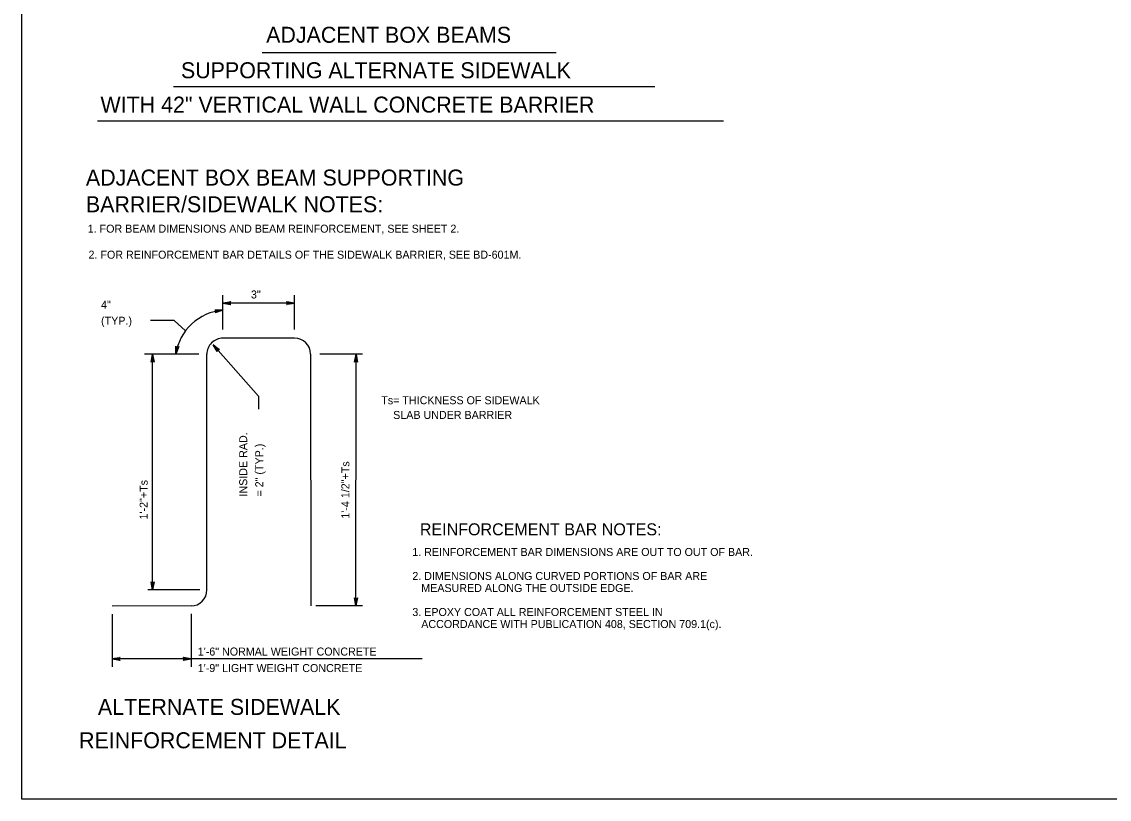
# Model space of a CAD drawing. Extents: x 639331 to 643089, y 299088 to 300975.
# Drawn here: x 641433.1 to 641840.8, y 299696.7 to 299988 of the extents above; entities that cross this region are included whole.
import ezdxf

# ---------------------------------------------------------------- set-up
doc = ezdxf.new("R2010")
doc.units = 0
doc.layers.add('1', color=7, linetype='Continuous')

msp = doc.modelspace()

# ---------------------------------------------------------------- linework, layer by layer
at = {"layer": '1'}
for p, q in [((641433.06, 299696.66), (641433.06, 300260.66)), ((641523.14, 299976.53), (641633.39, 299976.53)), ((641490, 299963.78), (641670.45, 299963.78)), ((641461.51, 299950.91), (641696.11, 299950.91)), ((641508.48, 299872.7), (641508.48, 299885.56)), ((641535.36, 299882.56), (641508.48, 299882.56)), ((641535.36, 299872.7), (641535.36, 299885.56)), ((641490.17, 299876.05), (641481.35, 299876.05)), ((641494.49, 299872.21), (641490.17, 299876.05)), ((641521.83, 299847.64), (641504.83, 299866.99)), ((641535.36, 299869.43), (641508.47, 299869.43)), ((641499.47, 299863.42), (641479.1, 299863.42)), ((641482.1, 299775.08), (641482.1, 299863.42)), ((641502.5, 299775.08), (641502.47, 299863.42)), ((641541.36, 299863.43), (641541.39, 299769.1)), ((641560.86, 299863.42), (641544.85, 299863.42)), ((641558.37, 299769.1), (641558.38, 299863.42)), ((641521.83, 299847.64), (641521.83, 299842.81)), ((641499.79, 299775.08), (641480.28, 299775.08)), ((641496.52, 299769.08), (641467, 299768.99)), ((641560.86, 299769.1), (641543.32, 299769.1)), ((641467, 299765.99), (641467, 299746.23)), ((641496.52, 299766.1), (641496.52, 299746.23)), ((641583.13, 299749.23), (641467, 299749.23)), ((642219.06, 299696.66), (641433.06, 299696.66))]:
    msp.add_line(p, q, dxfattribs=at)
for points in [[(641508.48, 299882.56), (641511.46, 299883.12), (641511.34, 299883.04), (641511.23, 299882.96), (641511.17, 299882.86), (641511.11, 299882.76), (641511.09, 299882.66), (641511.08, 299882.56), (641511.09, 299882.46), (641511.11, 299882.36), (641511.17, 299882.26), (641511.23, 299882.16), (641511.34, 299882.08), (641511.46, 299882), (641508.48, 299882.56), (641511.34, 299882.08), (641511.23, 299882.16), (641508.48, 299882.56), (641511.17, 299882.26), (641511.11, 299882.36), (641508.48, 299882.56), (641511.09, 299882.46), (641511.08, 299882.56), (641508.48, 299882.56), (641511.09, 299882.66), (641511.11, 299882.76), (641508.48, 299882.56), (641511.17, 299882.86), (641511.23, 299882.96), (641508.48, 299882.56), (641511.34, 299883.04)], [(641535.36, 299882.56), (641532.38, 299882), (641532.5, 299882.08), (641532.61, 299882.16), (641532.67, 299882.26), (641532.73, 299882.36), (641532.75, 299882.46), (641532.76, 299882.56), (641532.75, 299882.66), (641532.73, 299882.76), (641532.67, 299882.86), (641532.61, 299882.96), (641532.5, 299883.04), (641532.38, 299883.12), (641535.36, 299882.56), (641532.5, 299883.04), (641532.61, 299882.96), (641535.36, 299882.56), (641532.67, 299882.86), (641532.73, 299882.76), (641535.36, 299882.56), (641532.75, 299882.66), (641532.76, 299882.56), (641535.36, 299882.56), (641532.75, 299882.46), (641532.73, 299882.36), (641535.36, 299882.56), (641532.67, 299882.26), (641532.61, 299882.16), (641535.36, 299882.56), (641532.5, 299882.08)], [(641508.48, 299879.89), (641505.6, 299878.93), (641505.7, 299879.03), (641505.8, 299879.12), (641505.85, 299879.23), (641505.89, 299879.33), (641505.9, 299879.44), (641505.9, 299879.54), (641505.87, 299879.63), (641505.84, 299879.73), (641505.77, 299879.82), (641505.69, 299879.91), (641505.57, 299879.98), (641505.44, 299880.04), (641508.48, 299879.89), (641505.57, 299879.98), (641505.69, 299879.91), (641508.48, 299879.89), (641505.77, 299879.82), (641505.84, 299879.73), (641508.48, 299879.89), (641505.87, 299879.63), (641505.9, 299879.54), (641508.48, 299879.89), (641505.9, 299879.44), (641505.89, 299879.33), (641508.48, 299879.89), (641505.85, 299879.23), (641505.8, 299879.12), (641508.48, 299879.89), (641505.7, 299879.03)], [(641490.8, 299863.42), (641490.8, 299866.46), (641490.86, 299866.33), (641490.92, 299866.2), (641491.01, 299866.12), (641491.09, 299866.05), (641491.19, 299866.01), (641491.28, 299865.98), (641491.38, 299865.97), (641491.49, 299865.97), (641491.59, 299866.01), (641491.7, 299866.05), (641491.8, 299866.15), (641491.9, 299866.25), (641490.8, 299863.42), (641491.8, 299866.15), (641491.7, 299866.05), (641490.8, 299863.42), (641491.59, 299866.01), (641491.49, 299865.97), (641490.8, 299863.42), (641491.38, 299865.97), (641491.28, 299865.98), (641490.8, 299863.42), (641491.19, 299866.01), (641491.09, 299866.05), (641490.8, 299863.42), (641491.01, 299866.12), (641490.92, 299866.2), (641490.8, 299863.42), (641490.86, 299866.33)], [(641504.83, 299866.99), (641507.22, 299865.12), (641507.08, 299865.15), (641506.95, 299865.19), (641506.83, 299865.16), (641506.72, 299865.14), (641506.63, 299865.09), (641506.55, 299865.04), (641506.48, 299864.96), (641506.42, 299864.88), (641506.38, 299864.77), (641506.35, 299864.66), (641506.36, 299864.52), (641506.38, 299864.38), (641504.83, 299866.99), (641506.36, 299864.52), (641506.35, 299864.66), (641504.83, 299866.99), (641506.38, 299864.77), (641506.42, 299864.88), (641504.83, 299866.99), (641506.48, 299864.96), (641506.55, 299865.04), (641504.83, 299866.99), (641506.63, 299865.09), (641506.72, 299865.14), (641504.83, 299866.99), (641506.83, 299865.16), (641506.95, 299865.19), (641504.83, 299866.99), (641507.08, 299865.15)], [(641482.1, 299863.42), (641482.66, 299860.44), (641482.58, 299860.55), (641482.5, 299860.67), (641482.4, 299860.73), (641482.3, 299860.79), (641482.2, 299860.8), (641482.1, 299860.82), (641482, 299860.8), (641481.9, 299860.79), (641481.8, 299860.73), (641481.7, 299860.67), (641481.62, 299860.55), (641481.54, 299860.44), (641482.1, 299863.42), (641481.62, 299860.55), (641481.7, 299860.67), (641482.1, 299863.42), (641481.8, 299860.73), (641481.9, 299860.79), (641482.1, 299863.42), (641482, 299860.8), (641482.1, 299860.82), (641482.1, 299863.42), (641482.2, 299860.8), (641482.3, 299860.79), (641482.1, 299863.42), (641482.4, 299860.73), (641482.5, 299860.67), (641482.1, 299863.42), (641482.58, 299860.55)], [(641558.38, 299863.42), (641558.94, 299860.44), (641558.86, 299860.55), (641558.78, 299860.67), (641558.68, 299860.73), (641558.58, 299860.79), (641558.48, 299860.8), (641558.38, 299860.82), (641558.28, 299860.8), (641558.18, 299860.79), (641558.08, 299860.73), (641557.98, 299860.67), (641557.9, 299860.55), (641557.82, 299860.44), (641558.38, 299863.42), (641557.9, 299860.55), (641557.98, 299860.67), (641558.38, 299863.42), (641558.08, 299860.73), (641558.18, 299860.79), (641558.38, 299863.42), (641558.28, 299860.8), (641558.38, 299860.82), (641558.38, 299863.42), (641558.48, 299860.8), (641558.58, 299860.79), (641558.38, 299863.42), (641558.68, 299860.73), (641558.78, 299860.67), (641558.38, 299863.42), (641558.86, 299860.55)], [(641482.1, 299775.08), (641481.54, 299778.07), (641481.62, 299777.95), (641481.7, 299777.84), (641481.8, 299777.78), (641481.9, 299777.72), (641482, 299777.7), (641482.1, 299777.68), (641482.2, 299777.7), (641482.3, 299777.72), (641482.4, 299777.78), (641482.5, 299777.84), (641482.58, 299777.95), (641482.66, 299778.07), (641482.1, 299775.08), (641482.58, 299777.95), (641482.5, 299777.84), (641482.1, 299775.08), (641482.4, 299777.78), (641482.3, 299777.72), (641482.1, 299775.08), (641482.2, 299777.7), (641482.1, 299777.68), (641482.1, 299775.08), (641482, 299777.7), (641481.9, 299777.72), (641482.1, 299775.08), (641481.8, 299777.78), (641481.7, 299777.84), (641482.1, 299775.08), (641481.62, 299777.95)], [(641558.37, 299769.1), (641557.82, 299772.08), (641557.9, 299771.97), (641557.97, 299771.85), (641558.07, 299771.79), (641558.17, 299771.73), (641558.27, 299771.72), (641558.37, 299771.7), (641558.47, 299771.72), (641558.57, 299771.73), (641558.67, 299771.79), (641558.77, 299771.85), (641558.85, 299771.97), (641558.93, 299772.08), (641558.37, 299769.1), (641558.85, 299771.97), (641558.77, 299771.85), (641558.37, 299769.1), (641558.67, 299771.79), (641558.57, 299771.73), (641558.37, 299769.1), (641558.47, 299771.72), (641558.37, 299771.7), (641558.37, 299769.1), (641558.27, 299771.72), (641558.17, 299771.73), (641558.37, 299769.1), (641558.07, 299771.79), (641557.97, 299771.85), (641558.37, 299769.1), (641557.9, 299771.97)], [(641467, 299749.23), (641469.98, 299749.79), (641469.87, 299749.71), (641469.75, 299749.63), (641469.7, 299749.53), (641469.64, 299749.43), (641469.62, 299749.33), (641469.6, 299749.23), (641469.62, 299749.13), (641469.64, 299749.03), (641469.7, 299748.93), (641469.75, 299748.83), (641469.87, 299748.75), (641469.98, 299748.67), (641467, 299749.23), (641469.87, 299748.75), (641469.75, 299748.83), (641467, 299749.23), (641469.7, 299748.93), (641469.64, 299749.03), (641467, 299749.23), (641469.62, 299749.13), (641469.6, 299749.23), (641467, 299749.23), (641469.62, 299749.33), (641469.64, 299749.43), (641467, 299749.23), (641469.7, 299749.53), (641469.75, 299749.63), (641467, 299749.23), (641469.87, 299749.71)], [(641496.52, 299749.23), (641493.53, 299748.67), (641493.65, 299748.75), (641493.76, 299748.83), (641493.82, 299748.93), (641493.88, 299749.03), (641493.9, 299749.13), (641493.91, 299749.23), (641493.9, 299749.33), (641493.88, 299749.43), (641493.82, 299749.53), (641493.76, 299749.63), (641493.65, 299749.71), (641493.53, 299749.79), (641496.52, 299749.23), (641493.65, 299749.71), (641493.76, 299749.63), (641496.52, 299749.23), (641493.82, 299749.53), (641493.88, 299749.43), (641496.52, 299749.23), (641493.9, 299749.33), (641493.91, 299749.23), (641496.52, 299749.23), (641493.9, 299749.13), (641493.88, 299749.03), (641496.52, 299749.23), (641493.82, 299748.93), (641493.76, 299748.83), (641496.52, 299749.23), (641493.65, 299748.75)]]:
    msp.add_lwpolyline(points, dxfattribs=at)
for centre, radius, start, end in [((641510.01, 299860.52), 19.43, 94.5336, 171.4187), ((641508.47, 299863.43), 6, 90, 180.0143), ((641535.36, 299863.43), 6, 0.0141, 90), ((641496.5, 299775.08), 6, 270.1759, 0.0143)]:
    msp.add_arc(centre, radius, start, end, dxfattribs=at)

# ---------------------------------------------------------------- texts
for s, height, p in [('ADJACENT BOX BEAMS', 6, (641524.69, 299980.11)), ('SUPPORTING ALTERNATE SIDEWALK', 6, (641492.75, 299966.82)), ('WITH 42" VERTICAL WALL CONCRETE BARRIER', 6, (641462.58, 299953.95)), ('ADJACENT BOX BEAM SUPPORTING', 6, (641457.11, 299926.6)), ('BARRIER/SIDEWALK NOTES:', 6, (641457.11, 299916.6)), ('1. FOR BEAM DIMENSIONS AND BEAM REINFORCEMENT, SEE SHEET 2.', 3, (641457.79, 299908.95)), ('2. FOR REINFORCEMENT BAR DETAILS OF THE SIDEWALK BARRIER, SEE BD-601M.', 3, (641458.1, 299899.21)), ('3"', 3, (641519, 299884.3)), ('4"', 3, (641462.8, 299880.46)), ('(TYP.)', 3, (641462.8, 299874.46)), ('Ts= THICKNESS OF SIDEWALK', 3, (641567.86, 299844.66)), ('    SLAB UNDER BARRIER', 3, (641567.86, 299839.16)), ('REINFORCEMENT BAR NOTES:', 4.5, (641582.33, 299795.55)), ('1. REINFORCEMENT BAR DIMENSIONS ARE OUT TO OUT OF BAR.', 3, (641579.5, 299787.81)), ('2. DIMENSIONS ALONG CURVED PORTIONS OF BAR ARE', 3, (641579.5, 299778.81)), ('   MEASURED ALONG THE OUTSIDE EDGE.', 3, (641579.5, 299774.31)), ('3. EPOXY COAT ALL REINFORCEMENT STEEL IN', 3, (641579.5, 299765.31)), ('   ACCORDANCE WITH PUBLICATION 408, SECTION 709.1(c).', 3, (641579.5, 299760.81)), ('1\'-6" NORMAL WEIGHT CONCRETE', 3, (641499.05, 299750.5)), ('1\'-9" LIGHT WEIGHT CONCRETE', 3, (641499.05, 299744.31)), ('ALTERNATE SIDEWALK', 6, (641461.6, 299728.25)), ('REINFORCEMENT DETAIL', 6, (641454.55, 299715.75))]:
    msp.add_text(s, height=height, dxfattribs=at).set_placement(p)
for s, p in [('INSIDE RAD.', (641517.59, 299810.08)), ('= 2" (TYP.)', (641523.59, 299810.08)), ('1\'-4 1/2"+Ts', (641555.9, 299801.79)), ('1\'-2"+Ts', (641480.26, 299801.49))]:
    msp.add_text(s, height=3, rotation=90, dxfattribs=at).set_placement(p)

doc.saveas('drawing.dxf')
